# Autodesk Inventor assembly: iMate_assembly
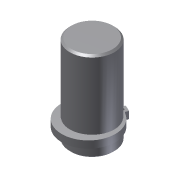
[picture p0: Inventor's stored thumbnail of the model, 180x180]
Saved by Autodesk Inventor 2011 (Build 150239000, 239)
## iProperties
Created: 2008-06
Part Number: iMate_assembly
Document SubType Name: Assembly
Designer: CADCIM
Author: CADCIM
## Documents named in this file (3)
- C:\Users\CADSoft\Desktop\part files\c17-inv-2011-prt\c17-tut02-inv-2011\iMate_assembly.iam
- C:\Inventor_2011\c17_inv_2010_07052010\Tutorial_2\Shaft.ipt
- C:\Inventor_2011\c17_inv_2010_07052010\Tutorial_2\circlip.ipt
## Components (2 placed, 2 different names)
1. Shaft:1
2. circlip:1
